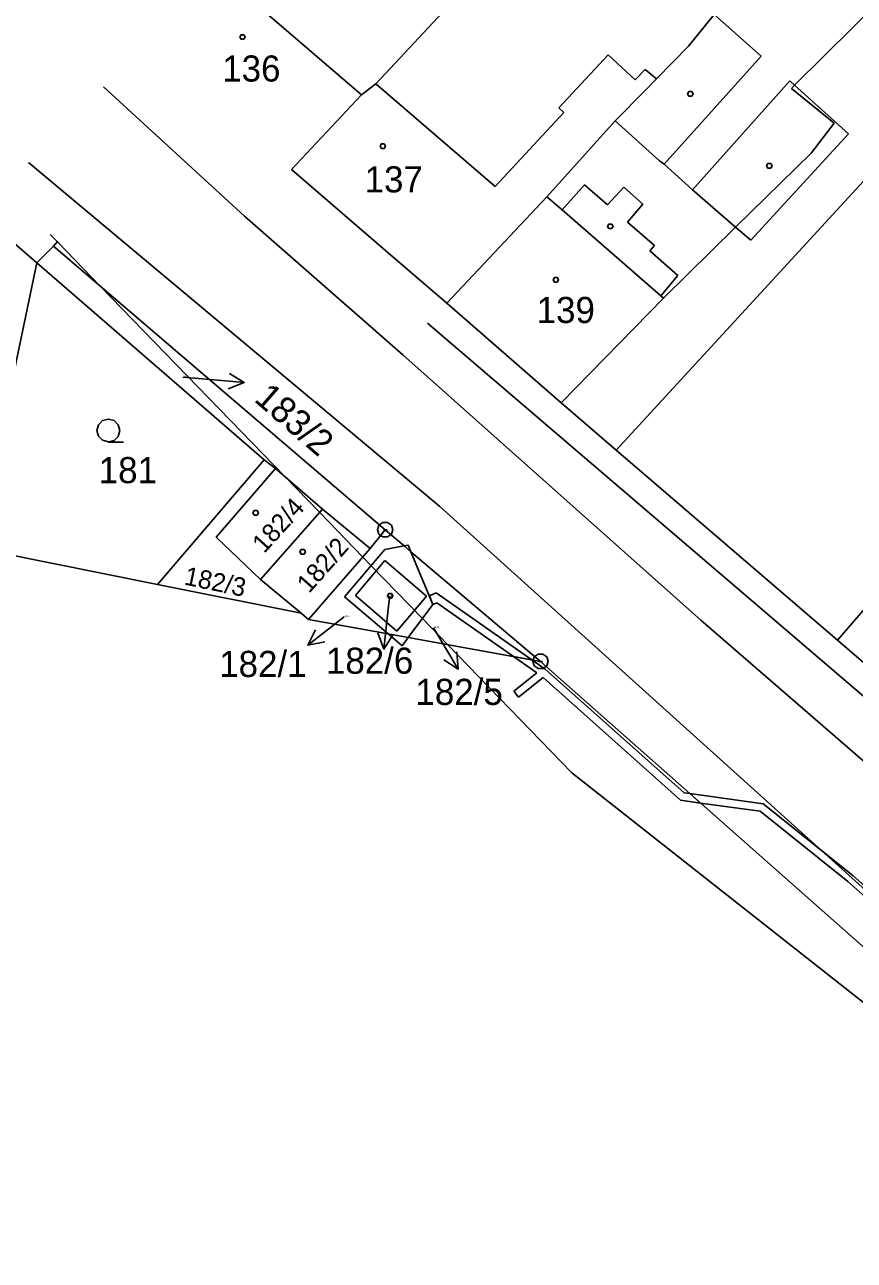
# Model space of a CAD drawing. Extents: x -755359 to -754474, y -1162585 to -1161655.
# Drawn here: x -754987.3 to -754933.3, y -1161780.5 to -1161700.1 of the extents above; entities that cross this region are included whole.
import ezdxf

# ---------------------------------------------------------------- set-up
doc = ezdxf.new("R2010")
doc.units = 0
for name, color, linetype in [('Vrstva 1', 7, 'Continuous'), ('Vrstva 11', 7, 'Continuous'), ('Vrstva 12', 7, 'Continuous'), ('Vrstva 13', 7, 'Continuous'), ('Vrstva 2', 7, 'Continuous'), ('Vrstva 3', 7, 'Continuous'), ('Vrstva 4', 7, 'Continuous'), ('Vrstva 5', 7, 'Continuous'), ('Vrstva 7', 7, 'Continuous'), ('Vrstva 8', 7, 'Continuous')]:
    doc.layers.add(name, color=color, linetype=linetype)

msp = doc.modelspace()

# ---------------------------------------------------------------- linework, layer by layer
at = {"layer": 'Vrstva 1'}
for p, q in [((-754937.15, -1161704.08), (-754916.55, -1161683.55)), ((-754948.77, -1161727.83), (-754912.31, -1161688.18)), ((-754956.37, -1161695.39), (-754964.42, -1161704)), ((-754944.06, -1161701.54), (-754942.4, -1161699.49)), ((-754946.15, -1161703.67), (-754944.06, -1161701.54)), ((-754946.95, -1161704.49), (-754946.15, -1161703.67)), ((-754964.42, -1161704), (-754965.35, -1161704.72)), ((-754948.83, -1161706.41), (-754946.95, -1161704.49)), ((-754937.36, -1161704.29), (-754937.15, -1161704.08)), ((-754934.57, -1161706.55), (-754937.36, -1161704.29)), ((-754965.35, -1161704.72), (-754969.9, -1161709.58)), ((-754953.28, -1161711.36), (-754948.83, -1161706.41)), ((-754936.08, -1161708.51), (-754934.57, -1161706.55)), ((-754941, -1161713.33), (-754936.08, -1161708.51)), ((-754969.9, -1161709.58), (-754969.9, -1161709.58)), ((-754963.77, -1161714.86), (-754969.9, -1161709.58)), ((-754959.79, -1161718.27), (-754953.28, -1161711.36)), ((-754986.49, -1161715.65), (-754989.82, -1161712.77)), ((-754945.68, -1161717.94), (-754941, -1161713.33)), ((-754985.41, -1161714.55), (-754986.49, -1161715.65)), ((-754985.41, -1161714.55), (-754985.11, -1161714.24)), ((-754985.41, -1161714.55), (-754985.41, -1161714.55)), ((-754963.8, -1161733.02), (-754985.41, -1161714.55)), ((-754985.11, -1161714.24), (-754985.11, -1161714.24)), ((-754963.77, -1161714.86), (-754959.79, -1161718.27)), ((-754986.49, -1161715.65), (-754990.38, -1161734.22)), ((-754971.69, -1161728.46), (-754986.49, -1161715.65)), ((-754914.5, -1161717.12), (-754934.36, -1161740.2)), ((-754945.68, -1161717.94), (-754952.34, -1161724.76)), ((-754952.34, -1161724.76), (-754959.79, -1161718.27)), ((-754924.16, -1161751.14), (-754961.05, -1161719.56)), ((-754961.05, -1161719.56), (-754961.05, -1161719.56)), ((-754952.34, -1161724.76), (-754948.77, -1161727.83)), ((-754934.36, -1161740.2), (-754948.77, -1161727.83)), ((-754978.64, -1161736.57), (-754971.69, -1161728.46)), ((-754971.69, -1161728.46), (-754970.94, -1161729.03)), ((-754970.94, -1161729.03), (-754974.81, -1161733.49)), ((-754967.88, -1161731.67), (-754970.94, -1161729.03)), ((-754971.93, -1161736.25), (-754967.88, -1161731.67)), ((-754967.88, -1161731.67), (-754964.78, -1161734.24)), ((-754974.81, -1161733.49), (-754971.93, -1161736.25)), ((-754963.8, -1161733.02), (-754964.78, -1161734.24)), ((-754962.57, -1161734.06), (-754963.8, -1161733.02)), ((-754990.38, -1161734.22), (-754978.64, -1161736.57)), ((-754964.78, -1161734.24), (-754968.79, -1161738.86)), ((-754966.45, -1161737.38), (-754963.82, -1161734.29)), ((-754963.82, -1161734.29), (-754962.57, -1161734.06)), ((-754962.13, -1161734.44), (-754962.57, -1161734.06)), ((-754953.69, -1161741.58), (-754962.13, -1161734.44)), ((-754962.13, -1161734.44), (-754960.7, -1161737.88)), ((-754978.64, -1161736.57), (-754969.27, -1161738.43)), ((-754969.27, -1161738.43), (-754971.93, -1161736.25)), ((-754963.61, -1161739.79), (-754966.45, -1161737.38)), ((-754960.7, -1161737.88), (-754962.32, -1161740.03)), ((-754968.79, -1161738.86), (-754969.27, -1161738.43)), ((-754968.79, -1161738.86), (-754963.61, -1161739.79)), ((-754963.61, -1161739.79), (-754962.32, -1161740.03)), ((-754962.32, -1161740.03), (-754953.69, -1161741.58)), ((-754934.36, -1161740.2), (-754923.04, -1161749.93)), ((-754953.69, -1161741.58), (-754855.01, -1161828.87))]:
    msp.add_line(p, q, dxfattribs=at)
at = {"layer": 'Vrstva 11'}
for p, q in [((-754985.61, -1161713.8), (-754985.15, -1161714.28)), ((-754985.15, -1161714.28), (-754982.36, -1161717.16)), ((-754982.36, -1161717.16), (-754970.36, -1161729.53)), ((-754970.36, -1161729.53), (-754968.07, -1161731.89)), ((-754968.07, -1161731.89), (-754965.26, -1161734.79)), ((-754965.26, -1161734.79), (-754964.72, -1161735.35)), ((-754964.72, -1161735.35), (-754961.38, -1161738.79)), ((-754961.38, -1161738.79), (-754959.73, -1161740.5)), ((-754959.73, -1161740.5), (-754951.65, -1161748.83)), ((-754951.65, -1161748.83), (-754905.2, -1161785.42))]:
    msp.add_line(p, q, dxfattribs=at)
at = {"layer": 'Vrstva 12'}
for p, q in [((-754971.61, -1161699.33), (-754965.35, -1161704.72)), ((-754949.3, -1161702.11), (-754952.5, -1161705.56)), ((-754947.54, -1161703.74), (-754949.3, -1161702.11)), ((-754946.88, -1161703.06), (-754947.54, -1161703.74)), ((-754946.95, -1161704.49), (-754946.15, -1161703.67)), ((-754946.15, -1161703.67), (-754946.88, -1161703.06)), ((-754964.42, -1161704), (-754965.35, -1161704.72)), ((-754964.42, -1161704), (-754956.65, -1161710.67)), ((-754948.83, -1161706.41), (-754946.95, -1161704.49)), ((-754965.35, -1161704.72), (-754969.9, -1161709.58)), ((-754965.35, -1161704.72), (-754969.9, -1161709.58)), ((-754952.17, -1161705.87), (-754956.65, -1161710.67)), ((-754952.5, -1161705.56), (-754952.17, -1161705.87)), ((-754953.28, -1161711.36), (-754948.83, -1161706.41)), ((-754969.9, -1161709.58), (-754969.9, -1161709.58)), ((-754963.77, -1161714.86), (-754969.9, -1161709.58)), ((-754959.79, -1161718.27), (-754953.28, -1161711.36)), ((-754959.79, -1161718.27), (-754953.28, -1161711.36)), ((-754953.28, -1161711.36), (-754952.29, -1161712.19)), ((-754952.29, -1161712.19), (-754945.87, -1161717.78)), ((-754963.77, -1161714.86), (-754959.79, -1161718.27)), ((-754945.68, -1161717.94), (-754952.34, -1161724.76)), ((-754945.87, -1161717.78), (-754945.68, -1161717.94)), ((-754952.34, -1161724.76), (-754959.79, -1161718.27)), ((-754970.94, -1161729.03), (-754974.81, -1161733.49)), ((-754967.88, -1161731.67), (-754970.94, -1161729.03)), ((-754971.93, -1161736.25), (-754967.88, -1161731.67)), ((-754971.93, -1161736.25), (-754967.88, -1161731.67)), ((-754967.88, -1161731.67), (-754964.78, -1161734.24)), ((-754974.81, -1161733.49), (-754971.93, -1161736.25)), ((-754964.78, -1161734.24), (-754968.79, -1161738.86)), ((-754965.75, -1161737.28), (-754963.83, -1161735.02)), ((-754963.83, -1161735.02), (-754961.12, -1161737.33)), ((-754969.27, -1161738.43), (-754971.93, -1161736.25)), ((-754963.05, -1161739.61), (-754965.75, -1161737.28)), ((-754961.12, -1161737.33), (-754963.05, -1161739.61)), ((-754968.79, -1161738.86), (-754969.27, -1161738.43))]:
    msp.add_line(p, q, dxfattribs=at)
at = {"layer": 'Vrstva 13'}
for p, q in [((-754960.93, -1161737.32), (-754960.49, -1161737.12)), ((-754960.7, -1161737.88), (-754960.93, -1161737.32)), ((-754960.49, -1161737.12), (-754954.26, -1161741.48)), ((-754960.45, -1161737.76), (-754960.7, -1161737.88)), ((-754955.46, -1161741.26), (-754960.45, -1161737.76)), ((-754953.94, -1161742.33), (-754955.46, -1161741.26)), ((-754955.46, -1161741.26), (-754954.26, -1161741.48)), ((-754954.26, -1161741.48), (-754955.46, -1161741.26)), ((-754954.26, -1161741.48), (-754953.4, -1161742.08)), ((-754955.43, -1161743.51), (-754953.94, -1161742.33)), ((-754953.4, -1161742.08), (-754944.34, -1161750.13)), ((-754953.53, -1161742.63), (-754955.13, -1161743.91)), ((-754944.58, -1161750.61), (-754953.53, -1161742.63)), ((-754955.13, -1161743.91), (-754955.43, -1161743.51)), ((-754944.34, -1161750.13), (-754943.97, -1161750.18)), ((-754943.97, -1161750.18), (-754939.19, -1161750.85)), ((-754943.97, -1161750.18), (-754943.28, -1161750.79)), ((-754943.28, -1161750.79), (-754943.97, -1161750.18)), ((-754943.28, -1161750.79), (-754944.58, -1161750.61)), ((-754939.4, -1161751.33), (-754943.28, -1161750.79)), ((-754939.19, -1161750.85), (-754933.37, -1161755.51)), ((-754933.69, -1161755.9), (-754939.4, -1161751.33)), ((-754907.13, -1161779.39), (-754933.69, -1161755.9)), ((-754933.37, -1161755.51), (-754906.81, -1161779.01))]:
    msp.add_line(p, q, dxfattribs=at)
at = {"layer": 'Vrstva 3'}
msp.add_lwpolyline([(-754981.82, -1161727.29), (-754982.2, -1161727.19), (-754982.47, -1161726.92), (-754982.57, -1161726.55), (-754982.47, -1161726.18), (-754982.2, -1161725.91), (-754981.83, -1161725.81), (-754981.46, -1161725.91), (-754981.19, -1161726.18), (-754981.09, -1161726.56), (-754981.19, -1161726.94), (-754981.46, -1161727.21), (-754981.84, -1161727.31), (-754980.84, -1161727.31)], dxfattribs=at)
at = {"layer": 'Vrstva 4'}
for p, q in [((-754971.61, -1161699.33), (-754965.35, -1161704.72)), ((-754939.32, -1161702.19), (-754942.4, -1161699.49)), ((-754949.3, -1161702.11), (-754952.5, -1161705.56)), ((-754947.54, -1161703.74), (-754949.3, -1161702.11)), ((-754945.65, -1161709.22), (-754939.32, -1161702.19)), ((-754946.88, -1161703.06), (-754947.54, -1161703.74)), ((-754946.15, -1161703.67), (-754946.88, -1161703.06)), ((-754972.97, -1161712.61), (-754982.15, -1161704.19)), ((-754982.15, -1161704.19), (-754982.15, -1161704.19)), ((-754964.42, -1161704), (-754956.65, -1161710.67)), ((-754937.46, -1161703.8), (-754943.8, -1161710.9)), ((-754937.15, -1161704.08), (-754937.46, -1161703.8)), ((-754933.64, -1161707.24), (-754937.15, -1161704.08)), ((-754952.17, -1161705.87), (-754956.65, -1161710.67)), ((-754952.5, -1161705.56), (-754952.17, -1161705.87)), ((-754945.94, -1161709.01), (-754948.83, -1161706.41)), ((-754940.01, -1161714.16), (-754933.64, -1161707.24)), ((-754987.03, -1161709.11), (-754987.03, -1161709.11)), ((-754987.03, -1161709.11), (-754960.25, -1161731.5)), ((-754945.65, -1161709.22), (-754945.94, -1161709.01)), ((-754943.8, -1161710.9), (-754945.65, -1161709.22)), ((-754952.29, -1161712.19), (-754950.83, -1161710.56)), ((-754950.83, -1161710.56), (-754949.33, -1161711.87)), ((-754949.33, -1161711.87), (-754948.26, -1161710.72)), ((-754948.26, -1161710.72), (-754947.03, -1161711.83)), ((-754943.8, -1161710.9), (-754941, -1161713.33)), ((-754953.28, -1161711.36), (-754952.29, -1161712.19)), ((-754952.29, -1161712.19), (-754945.87, -1161717.78)), ((-754947.03, -1161711.83), (-754948.04, -1161712.99)), ((-754962.66, -1161721.63), (-754972.97, -1161712.61)), ((-754948.04, -1161712.99), (-754946.27, -1161714.52)), ((-754941, -1161713.33), (-754940.01, -1161714.16)), ((-754946.27, -1161714.52), (-754946.57, -1161714.86)), ((-754946.57, -1161714.86), (-754944.75, -1161716.46)), ((-754944.75, -1161716.46), (-754945.87, -1161717.78)), ((-754945.87, -1161717.78), (-754945.68, -1161717.94)), ((-754962.66, -1161721.63), (-754943.25, -1161738.89)), ((-754931.36, -1161757.54), (-754960.25, -1161731.5)), ((-754962.57, -1161734.06), (-754962.3, -1161734.02)), ((-754962.3, -1161734.02), (-754962.13, -1161734.44)), ((-754965.75, -1161737.28), (-754963.83, -1161735.02)), ((-754963.83, -1161735.02), (-754961.12, -1161737.33)), ((-754963.05, -1161739.61), (-754965.75, -1161737.28)), ((-754961.12, -1161737.33), (-754963.05, -1161739.61)), ((-754943.25, -1161738.89), (-754926.26, -1161753.63)), ((-754962.71, -1161740.56), (-754963.61, -1161739.79)), ((-754962.32, -1161740.03), (-754962.71, -1161740.56))]:
    msp.add_line(p, q, dxfattribs=at)
at = {"layer": 'Vrstva 5'}
for points in [[(-754973.01, -1161700.8), (-754972.92, -1161700.95), (-754973.01, -1161701.1), (-754973.19, -1161701.1), (-754973.28, -1161700.95), (-754973.19, -1161700.8)], [(-754943.85, -1161704.5), (-754943.76, -1161704.65), (-754943.85, -1161704.8), (-754944.03, -1161704.8), (-754944.12, -1161704.65), (-754944.03, -1161704.5)], [(-754963.87, -1161707.9), (-754963.78, -1161708.05), (-754963.87, -1161708.2), (-754964.05, -1161708.2), (-754964.14, -1161708.05), (-754964.05, -1161707.9)], [(-754938.71, -1161709.19), (-754938.62, -1161709.34), (-754938.71, -1161709.49), (-754938.89, -1161709.49), (-754938.98, -1161709.34), (-754938.89, -1161709.19)], [(-754949.06, -1161713.12), (-754948.97, -1161713.27), (-754949.06, -1161713.42), (-754949.24, -1161713.42), (-754949.33, -1161713.27), (-754949.24, -1161713.12)], [(-754952.61, -1161716.6), (-754952.52, -1161716.75), (-754952.61, -1161716.9), (-754952.79, -1161716.9), (-754952.88, -1161716.75), (-754952.79, -1161716.6)], [(-754972.15, -1161731.76), (-754972.06, -1161731.91), (-754972.15, -1161732.06), (-754972.33, -1161732.06), (-754972.42, -1161731.91), (-754972.33, -1161731.76)], [(-754969.09, -1161734.3), (-754969, -1161734.45), (-754969.09, -1161734.6), (-754969.27, -1161734.6), (-754969.36, -1161734.45), (-754969.27, -1161734.3)], [(-754963.39, -1161737.16), (-754963.3, -1161737.31), (-754963.39, -1161737.46), (-754963.57, -1161737.46), (-754963.66, -1161737.31), (-754963.57, -1161737.16)]]:
    msp.add_lwpolyline(points, close=True, dxfattribs=at)
at = {"layer": 'Vrstva 7'}
for p, q in [((-754976.99, -1161723.08), (-754975.97, -1161723.17)), ((-754972.981, -1161723.432), (-754975.97, -1161723.17)), ((-754963.51, -1161737.34), (-754963.56, -1161737.79)), ((-754963.891, -1161740.772), (-754963.56, -1161737.79)), ((-754968.834, -1161740.527), (-754966.47, -1161738.68)), ((-754960.66, -1161739.4), (-754960.6, -1161739.5)), ((-754959.054, -1161742.071), (-754960.6, -1161739.5))]:
    msp.add_line(p, q, dxfattribs=at)
for points in [[(-754973.934, -1161722.846), (-754972.981, -1161723.432), (-754974.021, -1161723.843)], [(-754967.738, -1161740.305), (-754968.834, -1161740.527), (-754968.354, -1161739.517)], [(-754963.284, -1161739.833), (-754963.891, -1161740.772), (-754964.278, -1161739.723)], [(-754959.141, -1161740.956), (-754959.054, -1161742.071), (-754959.998, -1161741.472)]]:
    msp.add_lwpolyline(points, dxfattribs=at)
at = {"layer": 'Vrstva 8'}
for p, q in [((-754963.92, -1161733.02), (-754963.68, -1161733.02)), ((-754953.81, -1161741.58), (-754953.57, -1161741.58))]:
    msp.add_line(p, q, dxfattribs=at)
for points in [[(-754963.65, -1161732.54), (-754963.4, -1161732.72), (-754963.3, -1161733.01), (-754963.4, -1161733.3), (-754963.65, -1161733.48), (-754963.96, -1161733.48), (-754964.21, -1161733.3), (-754964.31, -1161733.01), (-754964.21, -1161732.72), (-754963.96, -1161732.54)], [(-754953.54, -1161741.1), (-754953.29, -1161741.28), (-754953.19, -1161741.57), (-754953.29, -1161741.86), (-754953.54, -1161742.04), (-754953.85, -1161742.04), (-754954.1, -1161741.86), (-754954.2, -1161741.57), (-754954.1, -1161741.28), (-754953.85, -1161741.1)]]:
    msp.add_lwpolyline(points, close=True, dxfattribs=at)

# ---------------------------------------------------------------- texts
at = {"layer": 'Vrstva 2'}
for s, height, p in [('136', 1.7, (-754974.417, -1161703.85)), ('137', 1.7, (-754965.147, -1161711.06)), ('139', 1.7, (-754953.947, -1161719.56)), ('183/2', 0.1, (-754976.967, -1161723.08)), ('181', 1.7, (-754982.457, -1161729.98)), ('182/6', 0.1, (-754963.697, -1161737.34)), ('182/1', 0.1, (-754966.447, -1161738.68)), ('182/5', 0.1, (-754960.637, -1161739.4))]:
    msp.add_text(s, height=height, dxfattribs=at).set_placement(p)
for s, rotation, p in [('182/4', 47.72738, (-754971.684, -1161734.595)), ('182/2', 48.58682, (-754968.767, -1161737.202)), ('182/3', 348.30104, (-754976.949, -1161736.566))]:
    msp.add_text(s, height=1.2, rotation=rotation, dxfattribs=at).set_placement(p)
at = {"layer": 'Vrstva 7'}
msp.add_text('183/2', height=1.7, rotation=319.0229, dxfattribs=at).set_placement((-754972.408, -1161724.601))
for s, p in [('182/6', (-754967.666, -1161742.38)), ('182/1', (-754974.613, -1161742.59)), ('182/5', (-754961.837, -1161744.41))]:
    msp.add_text(s, height=1.7, dxfattribs=at).set_placement(p)

doc.saveas('drawing.dxf')
